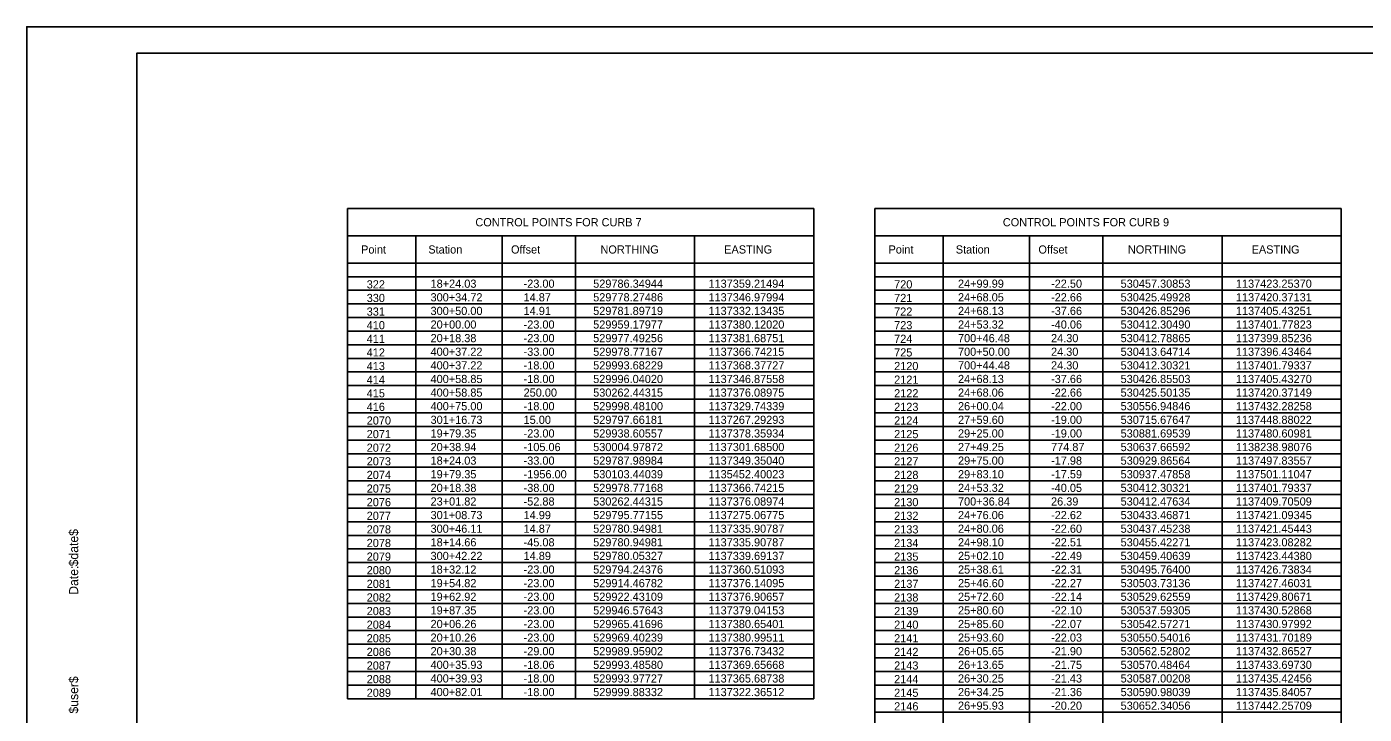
# Model space of a CAD drawing. Extents: x 0 to 850, y 0 to 550.
# Drawn here: x -0.1 to 491.2, y 297.4 to 549.9 of the extents above; entities that cross this region are included whole.
import ezdxf

# ---------------------------------------------------------------- set-up
doc = ezdxf.new("R2010")
doc.units = 0
for name, color, linetype in [('ANNOTATION', 7, 'Continuous'), ('BORDER', 7, 'Continuous'), ('Default', 7, 'Continuous'), ('H_V CONTROLS', 7, 'Continuous'), ('PLOT BOUNDARY', 7, 'Continuous')]:
    doc.layers.add(name, color=color, linetype=linetype)

msp = doc.modelspace()

# ---------------------------------------------------------------- linework, layer by layer
at = {"layer": 'BORDER'}
for p, q in [((840.33, 540.24), (40.33, 540.24)), ((40.33, 540.24), (40.33, 15.24))]:
    msp.add_line(p, q, dxfattribs=at)
at = {"layer": 'Default'}
msp.add_lwpolyline([(40.33, 15.24), (790.33, 15.24), (790.33, 540.26), (40.33, 540.26)], close=True, dxfattribs=at)
at = {"layer": 'H_V CONTROLS'}
for p, q in [((117.72, 483.15), (288.95, 483.15)), ((117.72, 483.15), (117.72, 303.15)), ((288.95, 483.15), (288.95, 303.15)), ((311.48, 483.15), (482.71, 483.15)), ((311.48, 483.15), (311.48, 208.15)), ((482.71, 483.15), (482.71, 208.15)), ((117.72, 473.15), (288.95, 473.15)), ((142.76, 473.15), (142.76, 303.15)), ((174.53, 473.15), (174.53, 303.15)), ((201.45, 473.15), (201.45, 303.15)), ((245.2, 473.15), (245.2, 303.15)), ((311.48, 473.15), (482.71, 473.15)), ((336.52, 473.15), (336.52, 208.15)), ((368.3, 473.15), (368.3, 208.15)), ((395.21, 473.15), (395.21, 208.15)), ((438.96, 473.15), (438.96, 208.15)), ((117.72, 463.15), (288.95, 463.15)), ((311.48, 463.15), (482.71, 463.15)), ((117.72, 458.15), (288.95, 458.15)), ((311.48, 458.15), (482.71, 458.15)), ((117.72, 453.15), (288.95, 453.15)), ((311.48, 453.15), (482.71, 453.15)), ((117.72, 448.15), (288.95, 448.15)), ((311.48, 448.15), (482.71, 448.15)), ((117.72, 443.15), (288.95, 443.15)), ((311.48, 443.15), (482.71, 443.15)), ((117.72, 438.15), (288.95, 438.15)), ((311.48, 438.15), (482.71, 438.15)), ((117.72, 433.15), (288.95, 433.15)), ((311.48, 433.15), (482.71, 433.15)), ((117.72, 428.15), (288.95, 428.15)), ((311.48, 428.15), (482.71, 428.15)), ((117.72, 423.15), (288.95, 423.15)), ((311.48, 423.15), (482.71, 423.15)), ((117.72, 418.15), (288.95, 418.15)), ((311.48, 418.15), (482.71, 418.15)), ((117.72, 413.15), (288.95, 413.15)), ((311.48, 413.15), (482.71, 413.15)), ((117.72, 408.15), (288.95, 408.15)), ((311.48, 408.15), (482.71, 408.15)), ((117.72, 403.15), (288.95, 403.15)), ((311.48, 403.15), (482.71, 403.15)), ((117.72, 398.15), (288.95, 398.15)), ((311.48, 398.15), (482.71, 398.15)), ((117.72, 393.15), (288.95, 393.15)), ((311.48, 393.15), (482.71, 393.15)), ((117.72, 388.15), (288.95, 388.15)), ((311.48, 388.15), (482.71, 388.15)), ((117.72, 383.15), (288.95, 383.15)), ((311.48, 383.15), (482.71, 383.15)), ((117.72, 378.15), (288.95, 378.15)), ((311.48, 378.15), (482.71, 378.15)), ((117.72, 373.15), (288.95, 373.15)), ((311.48, 373.15), (482.71, 373.15)), ((117.72, 368.15), (288.95, 368.15)), ((311.48, 368.15), (482.71, 368.15)), ((117.72, 363.15), (288.95, 363.15)), ((311.48, 363.15), (482.71, 363.15)), ((117.72, 358.15), (288.95, 358.15)), ((117.72, 358.15), (288.95, 358.15)), ((311.48, 358.15), (482.71, 358.15)), ((311.48, 358.15), (482.71, 358.15)), ((117.72, 353.15), (288.95, 353.15)), ((311.48, 353.15), (482.71, 353.15)), ((117.72, 348.15), (288.95, 348.15)), ((311.48, 348.15), (482.71, 348.15)), ((117.72, 343.15), (288.95, 343.15)), ((311.48, 343.15), (482.71, 343.15)), ((117.72, 338.15), (288.95, 338.15)), ((311.48, 338.15), (482.71, 338.15)), ((117.72, 333.15), (288.95, 333.15)), ((311.48, 333.15), (482.71, 333.15)), ((117.72, 328.15), (288.95, 328.15)), ((311.48, 328.15), (482.71, 328.15)), ((117.72, 323.15), (288.95, 323.15)), ((311.48, 323.15), (482.71, 323.15)), ((117.72, 318.15), (288.95, 318.15)), ((311.48, 318.15), (482.71, 318.15)), ((117.72, 313.15), (288.95, 313.15)), ((311.48, 313.15), (482.71, 313.15)), ((117.72, 308.15), (288.95, 308.15)), ((311.48, 308.15), (482.71, 308.15)), ((117.72, 303.15), (288.95, 303.15)), ((311.48, 303.15), (482.71, 303.15)), ((311.48, 298.15), (482.71, 298.15))]:
    msp.add_line(p, q, dxfattribs=at)
at = {"layer": 'PLOT BOUNDARY'}
msp.add_lwpolyline([(-0.13, -0.05), (849.87, -0.05), (849.87, 549.95), (-0.13, 549.95)], close=True, dxfattribs=at)

# ---------------------------------------------------------------- texts
at = {"layer": 'ANNOTATION'}
for s, p in [('18+24.03', (148.21, 454.09)), ('-23.00', (182.39, 454.09)), ('529786.34944', (207.95, 454.09)), ('1137359.21494', (250.3, 454.09)), ('24+99.99', (341.97, 454.09)), ('-22.50', (376.16, 454.09)), ('530457.30853', (401.71, 454.09)), ('1137423.25370', (444.06, 454.09)), ('322', (124.75, 453.84)), ('300+34.72', (148.21, 449.09)), ('14.87', (182.39, 449.09)), ('529778.27486', (207.95, 449.09)), ('1137346.97994', (250.3, 449.09)), ('720', (318.51, 453.84)), ('24+68.05', (341.97, 449.09)), ('-22.66', (376.16, 449.09)), ('530425.49928', (401.71, 449.09)), ('1137420.37131', (444.06, 449.09)), ('330', (124.75, 448.84)), ('300+50.00', (148.21, 444.09)), ('14.91', (182.39, 444.09)), ('529781.89719', (207.95, 444.09)), ('1137332.13435', (250.3, 444.09)), ('721', (318.51, 448.84)), ('24+68.13', (341.97, 444.09)), ('-37.66', (376.16, 444.09)), ('530426.85296', (401.71, 444.09)), ('1137405.43251', (444.06, 444.09)), ('331', (124.75, 443.84)), ('722', (318.51, 443.84)), ('410', (124.75, 438.84)), ('20+00.00', (148.21, 439.09)), ('-23.00', (182.39, 439.09)), ('529959.17977', (207.95, 439.09)), ('1137380.12020', (250.3, 439.09)), ('723', (318.51, 438.84)), ('24+53.32', (341.97, 439.09)), ('-40.06', (376.16, 439.09)), ('530412.30490', (401.71, 439.09)), ('1137401.77823', (444.06, 439.09)), ('411', (124.75, 433.84)), ('20+18.38', (148.21, 434.09)), ('-23.00', (182.39, 434.09)), ('529977.49256', (207.95, 434.09)), ('1137381.68751', (250.3, 434.09)), ('724', (318.51, 433.84)), ('700+46.48', (341.97, 434.09)), ('24.30', (376.16, 434.09)), ('530412.78865', (401.71, 434.09)), ('1137399.85236', (444.06, 434.09)), ('412', (124.75, 428.84)), ('400+37.22', (148.21, 429.09)), ('-33.00', (182.39, 429.09)), ('529978.77167', (207.95, 429.09)), ('1137366.74215', (250.3, 429.09)), ('725', (318.51, 428.84)), ('700+50.00', (341.97, 429.09)), ('24.30', (376.16, 429.09)), ('530413.64714', (401.71, 429.09)), ('1137396.43464', (444.06, 429.09)), ('413', (124.75, 423.84)), ('400+37.22', (148.21, 424.09)), ('-18.00', (182.39, 424.09)), ('529993.68229', (207.95, 424.09)), ('1137368.37727', (250.3, 424.09)), ('2120', (318.51, 423.84)), ('700+44.48', (341.97, 424.09)), ('24.30', (376.16, 424.09)), ('530412.30321', (401.71, 424.09)), ('1137401.79337', (444.06, 424.09)), ('414', (124.75, 418.84)), ('400+58.85', (148.21, 419.09)), ('-18.00', (182.39, 419.09)), ('529996.04020', (207.95, 419.09)), ('1137346.87558', (250.3, 419.09)), ('2121', (318.51, 418.84)), ('24+68.13', (341.97, 419.09)), ('-37.66', (376.16, 419.09)), ('530426.85503', (401.71, 419.09)), ('1137405.43270', (444.06, 419.09)), ('415', (124.75, 413.84)), ('400+58.85', (148.21, 414.09)), ('250.00', (182.39, 414.09)), ('530262.44315', (207.95, 414.09)), ('1137376.08975', (250.3, 414.09)), ('2122', (318.51, 413.84)), ('24+68.06', (341.97, 414.09)), ('-22.66', (376.16, 414.09)), ('530425.50135', (401.71, 414.09)), ('1137420.37149', (444.06, 414.09)), ('416', (124.75, 408.84)), ('400+75.00', (148.21, 409.09)), ('-18.00', (182.39, 409.09)), ('529998.48100', (207.95, 409.09)), ('1137329.74339', (250.3, 409.09)), ('2123', (318.51, 408.84)), ('26+00.04', (341.97, 409.09)), ('-22.00', (376.16, 409.09)), ('530556.94846', (401.71, 409.09)), ('1137432.28258', (444.06, 409.09)), ('2070', (124.75, 403.84)), ('301+16.73', (148.21, 404.09)), ('15.00', (182.39, 404.09)), ('529797.66181', (207.95, 404.09)), ('1137267.29293', (250.3, 404.09)), ('2124', (318.51, 403.84)), ('27+59.60', (341.97, 404.09)), ('-19.00', (376.16, 404.09)), ('530715.67647', (401.71, 404.09)), ('1137448.88022', (444.06, 404.09)), ('2071', (124.75, 398.85)), ('19+79.35', (148.21, 399.09)), ('-23.00', (182.39, 399.09)), ('529938.60557', (207.95, 399.09)), ('1137378.35934', (250.3, 399.09)), ('2125', (318.51, 398.85)), ('29+25.00', (341.97, 399.09)), ('-19.00', (376.16, 399.09)), ('530881.69539', (401.71, 399.09)), ('1137480.60981', (444.06, 399.09)), ('2072', (124.75, 393.85)), ('20+38.94', (148.21, 394.09)), ('-105.06', (182.39, 394.09)), ('530004.97872', (207.95, 394.09)), ('1137301.68500', (250.3, 394.09)), ('2126', (318.51, 393.85)), ('27+49.25', (341.97, 394.09)), ('774.87', (376.16, 394.09)), ('530637.66592', (401.71, 394.09)), ('1138238.98076', (444.06, 394.09)), ('2073', (124.75, 388.85)), ('18+24.03', (148.21, 389.1)), ('-33.00', (182.39, 389.1)), ('529787.98984', (207.95, 389.1)), ('1137349.35040', (250.3, 389.1)), ('2127', (318.51, 388.85)), ('29+75.00', (341.97, 389.1)), ('-17.98', (376.16, 389.1)), ('530929.86564', (401.71, 389.1)), ('1137497.83557', (444.06, 389.1)), ('2074', (124.75, 383.85)), ('19+79.35', (148.21, 384.1)), ('-1956.00', (182.39, 384.1)), ('530103.44039', (207.95, 384.1)), ('1135452.40023', (250.3, 384.1)), ('2128', (318.51, 383.85)), ('29+83.10', (341.97, 384.1)), ('-17.59', (376.16, 384.1)), ('530937.47858', (401.71, 384.1)), ('1137501.11047', (444.06, 384.1)), ('2075', (124.75, 378.85)), ('20+18.38', (148.21, 379.1)), ('-38.00', (182.39, 379.1)), ('529978.77168', (207.95, 379.1)), ('1137366.74215', (250.3, 379.1)), ('2129', (318.51, 378.85)), ('24+53.32', (341.97, 379.1)), ('-40.05', (376.16, 379.1)), ('530412.30321', (401.71, 379.1)), ('1137401.79337', (444.06, 379.1)), ('2076', (124.75, 373.85)), ('23+01.82', (148.21, 374.1)), ('-52.88', (182.39, 374.1)), ('530262.44315', (207.95, 374.1)), ('1137376.08974', (250.3, 374.1)), ('2130', (318.51, 373.85)), ('700+36.84', (341.97, 374.1)), ('26.39', (376.16, 374.1)), ('530412.47634', (401.71, 374.1)), ('1137409.70509', (444.06, 374.1)), ('2077', (124.75, 368.85)), ('301+08.73', (148.21, 369.1)), ('14.99', (182.39, 369.1)), ('529795.77155', (207.95, 369.1)), ('1137275.06775', (250.3, 369.1)), ('2132', (318.51, 368.85)), ('24+76.06', (341.97, 369.1)), ('-22.62', (376.16, 369.1)), ('530433.46871', (401.71, 369.1)), ('1137421.09345', (444.06, 369.1)), ('2078', (124.75, 363.85)), ('300+46.11', (148.21, 364.1)), ('14.87', (182.39, 364.1)), ('529780.94981', (207.95, 364.1)), ('1137335.90787', (250.3, 364.1)), ('2133', (318.51, 363.85)), ('24+80.06', (341.97, 364.1)), ('-22.60', (376.16, 364.1)), ('530437.45238', (401.71, 364.1)), ('1137421.45443', (444.06, 364.1)), ('2078', (124.75, 358.85)), ('18+14.66', (148.21, 359.1)), ('-45.08', (182.39, 359.1)), ('529780.94981', (207.95, 359.1)), ('1137335.90787', (250.3, 359.1)), ('2134', (318.51, 358.85)), ('24+98.10', (341.97, 359.1)), ('-22.51', (376.16, 359.1)), ('530455.42271', (401.71, 359.1)), ('1137423.08282', (444.06, 359.1)), ('2079', (124.75, 353.85)), ('300+42.22', (148.21, 354.1)), ('14.89', (182.39, 354.1)), ('529780.05327', (207.95, 354.1)), ('1137339.69137', (250.3, 354.1)), ('2135', (318.51, 353.85)), ('25+02.10', (341.97, 354.1)), ('-22.49', (376.16, 354.1)), ('530459.40639', (401.71, 354.1)), ('1137423.44380', (444.06, 354.1)), ('2080', (124.75, 348.85)), ('18+32.12', (148.21, 349.1)), ('-23.00', (182.39, 349.1)), ('529794.24376', (207.95, 349.1)), ('1137360.51093', (250.3, 349.1)), ('2136', (318.51, 348.85)), ('25+38.61', (341.97, 349.1)), ('-22.31', (376.16, 349.1)), ('530495.76400', (401.71, 349.1)), ('1137426.73834', (444.06, 349.1)), ('2081', (124.75, 343.85)), ('19+54.82', (148.21, 344.1)), ('-23.00', (182.39, 344.1)), ('529914.46782', (207.95, 344.1)), ('1137376.14095', (250.3, 344.1)), ('2137', (318.51, 343.85)), ('25+46.60', (341.97, 344.1)), ('-22.27', (376.16, 344.1)), ('530503.73136', (401.71, 344.1)), ('1137427.46031', (444.06, 344.1)), ('2082', (124.75, 338.85)), ('19+62.92', (148.21, 339.1)), ('-23.00', (182.39, 339.1)), ('529922.43109', (207.95, 339.1)), ('1137376.90657', (250.3, 339.1)), ('2138', (318.51, 338.85)), ('25+72.60', (341.97, 339.1)), ('-22.14', (376.16, 339.1)), ('530529.62559', (401.71, 339.1)), ('1137429.80671', (444.06, 339.1)), ('2083', (124.75, 333.85)), ('19+87.35', (148.21, 334.1)), ('-23.00', (182.39, 334.1)), ('529946.57643', (207.95, 334.1)), ('1137379.04153', (250.3, 334.1)), ('2139', (318.51, 333.85)), ('25+80.60', (341.97, 334.1)), ('-22.10', (376.16, 334.1)), ('530537.59305', (401.71, 334.1)), ('1137430.52868', (444.06, 334.1)), ('2084', (124.75, 328.85)), ('20+06.26', (148.21, 329.1)), ('-23.00', (182.39, 329.1)), ('529965.41696', (207.95, 329.1)), ('1137380.65401', (250.3, 329.1)), ('2140', (318.51, 328.85)), ('25+85.60', (341.97, 329.1)), ('-22.07', (376.16, 329.1)), ('530542.57271', (401.71, 329.1)), ('1137430.97992', (444.06, 329.1)), ('2085', (124.75, 323.85)), ('20+10.26', (148.21, 324.1)), ('-23.00', (182.39, 324.1)), ('529969.40239', (207.95, 324.1)), ('1137380.99511', (250.3, 324.1)), ('2141', (318.51, 323.85)), ('25+93.60', (341.97, 324.1)), ('-22.03', (376.16, 324.1)), ('530550.54016', (401.71, 324.1)), ('1137431.70189', (444.06, 324.1)), ('2086', (124.75, 318.85)), ('20+30.38', (148.21, 319.1)), ('-29.00', (182.39, 319.1)), ('529989.95902', (207.95, 319.1)), ('1137376.73432', (250.3, 319.1)), ('2142', (318.51, 318.85)), ('26+05.65', (341.97, 319.1)), ('-21.90', (376.16, 319.1)), ('530562.52802', (401.71, 319.1)), ('1137432.86527', (444.06, 319.1)), ('2087', (124.75, 313.85)), ('400+35.93', (148.21, 314.1)), ('-18.06', (182.39, 314.1)), ('529993.48580', (207.95, 314.1)), ('1137369.65668', (250.3, 314.1)), ('2143', (318.51, 313.85)), ('26+13.65', (341.97, 314.1)), ('-21.75', (376.16, 314.1)), ('530570.48464', (401.71, 314.1)), ('1137433.69730', (444.06, 314.1)), ('2088', (124.75, 308.85)), ('400+39.93', (148.21, 309.1)), ('-18.00', (182.39, 309.1)), ('529993.97727', (207.95, 309.1)), ('1137365.68738', (250.3, 309.1)), ('2144', (318.51, 308.85)), ('26+30.25', (341.97, 309.1)), ('-21.43', (376.16, 309.1)), ('530587.00208', (401.71, 309.1)), ('1137435.42456', (444.06, 309.1)), ('2089', (124.75, 303.85)), ('400+82.01', (148.21, 304.1)), ('-18.00', (182.39, 304.1)), ('529999.88332', (207.95, 304.1)), ('1137322.36512', (250.3, 304.1)), ('2145', (318.51, 303.85)), ('26+34.25', (341.97, 304.1)), ('-21.36', (376.16, 304.1)), ('530590.98039', (401.71, 304.1)), ('1137435.84057', (444.06, 304.1)), ('2146', (318.51, 298.85)), ('26+95.93', (341.97, 299.1)), ('-20.20', (376.16, 299.1)), ('530652.34056', (401.71, 299.1)), ('1137442.25709', (444.06, 299.1))]:
    msp.add_text(s, height=3, rotation=360, dxfattribs=at).set_placement(p)
at = {"layer": 'BORDER'}
for s, p in [('$date$', (18.76, 351.77)), ('Date:', (18.76, 341.33)), ('$user$', (18.76, 297.7))]:
    msp.add_text(s, height=3.348, rotation=90, dxfattribs=at).set_placement(p)
at = {"layer": 'H_V CONTROLS'}
for s, p in [('CONTROL POINTS FOR CURB 7', (164.68, 476.65)), ('CONTROL POINTS FOR CURB 9', (358.44, 476.65)), ('Point', (122.69, 466.65)), ('Station', (147.39, 466.65)), ('Offset', (177.76, 466.65)), ('NORTHING', (210.63, 466.65)), ('EASTING', (256.08, 466.65)), ('Point', (316.45, 466.65)), ('Station', (341.15, 466.65)), ('Offset', (371.52, 466.65)), ('NORTHING', (404.39, 466.65)), ('EASTING', (449.84, 466.65))]:
    msp.add_text(s, height=3, rotation=360, dxfattribs=at).set_placement(p)

doc.saveas('drawing.dxf')
